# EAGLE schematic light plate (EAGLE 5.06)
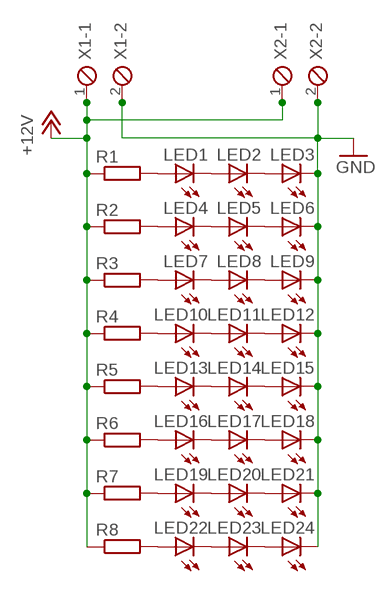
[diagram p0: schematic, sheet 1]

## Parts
LED1  LED5MM  [LED5MM]
LED2  LED5MM  [LED5MM]
LED3  LED5MM  [LED5MM]
LED4  LED5MM  [LED5MM]
LED5  LED5MM  [LED5MM]
LED6  LED5MM  [LED5MM]
LED7  LED5MM  [LED5MM]
LED8  LED5MM  [LED5MM]
LED9  LED5MM  [LED5MM]
LED10  LED5MM  [LED5MM]
LED11  LED5MM  [LED5MM]
LED12  LED5MM  [LED5MM]
LED13  LED5MM  [LED5MM]
LED14  LED5MM  [LED5MM]
LED15  LED5MM  [LED5MM]
LED16  LED5MM  [LED5MM]
LED17  LED5MM  [LED5MM]
LED18  LED5MM  [LED5MM]
LED19  LED5MM  [LED5MM]
LED20  LED5MM  [LED5MM]
LED21  LED5MM  [LED5MM]
LED22  LED5MM  [LED5MM]
LED23  LED5MM  [LED5MM]
LED24  LED5MM  [LED5MM]
R1  R-EU_0207/10  [0207/10]
R2  R-EU_0207/10  [0207/10]
R3  R-EU_0207/10  [0207/10]
R4  R-EU_0207/10  [0207/10]
R5  R-EU_0207/10  [0207/10]
R6  R-EU_0207/10  [0207/10]
R7  R-EU_0207/10  [0207/10]
R8  R-EU_0207/10  [0207/10]
X1  MPT2  [2POL254]
X2  MPT2  [2POL254]

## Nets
+12V: R1.1 R2.1 R3.1 R4.1 R5.1 R6.1 R7.1 R8.1 X1.1 X2.1
GND: LED3.K(C) LED6.K(C) LED9.K(C) LED12.K(C) LED15.K(C) LED18.K(C) LED21.K(C) LED24.K(C) X1.2 X2.2
N$1: LED1.K(C) LED2.A
N$2: LED2.K(C) LED3.A
N$3: LED4.K(C) LED5.A
N$4: LED5.K(C) LED6.A
N$5: LED7.K(C) LED8.A
N$6: LED8.K(C) LED9.A
N$7: LED10.K(C) LED11.A
N$8: LED11.K(C) LED12.A
N$9: LED13.K(C) LED14.A
N$10: LED14.K(C) LED15.A
N$11: LED16.K(C) LED17.A
N$12: LED17.K(C) LED18.A
N$13: LED19.K(C) LED20.A
N$14: LED20.K(C) LED21.A
N$15: LED22.K(C) LED23.A
N$16: LED23.K(C) LED24.A
N$17: LED1.A R1.2
N$18: LED4.A R2.2
N$19: LED7.A R3.2
N$20: LED10.A R4.2
N$21: LED13.A R5.2
N$22: LED16.A R6.2
N$23: LED19.A R7.2
N$24: LED22.A R8.2

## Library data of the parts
LED1-LED24 = led:LED: LED
R1-R8 = rcl:R-EU_: RESISTOR, European symbol
X1 X2 = con-phoenix-254:MPT2: PHOENIX CONNECTOR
